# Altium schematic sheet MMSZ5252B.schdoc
size 127 x 101 mm
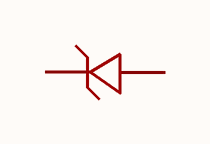
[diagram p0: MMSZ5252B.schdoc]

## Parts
ZD?  mmsz5252b_c21537  [SOD-123_L2.8-W1.8-LS3.7-RD]  (value not drawn)

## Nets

Not connected (* = marked no-connect by the designer): ZD? 1(K) 2(A)

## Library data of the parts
ZD? = mmsz5252b_c21537: 二极管配置:1个独立式;稳压值(标称值):24V;稳压值(范围):22.8V~25.2V;耗散功率(Pd):350mW;; Manufacturer: CJ(江苏长电/长晶); AddInBom: yes; ModelId: 7884390a25fb4c08947731ebfba7e3f8; ModelTransform: 144.8816,62.992,0,0,0,0,0,0,0; Diode Configuration: 1个独立式; Zener Voltage(Nom): 24V; Reverse Leakage Current (Ir): 100nA; Pd - Power Dissipation: 350mW; Impedance(Zzt): 33Ω; Impedance(Zzk): 600Ω; Operating Junction Temperature Range: -65℃~+150℃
